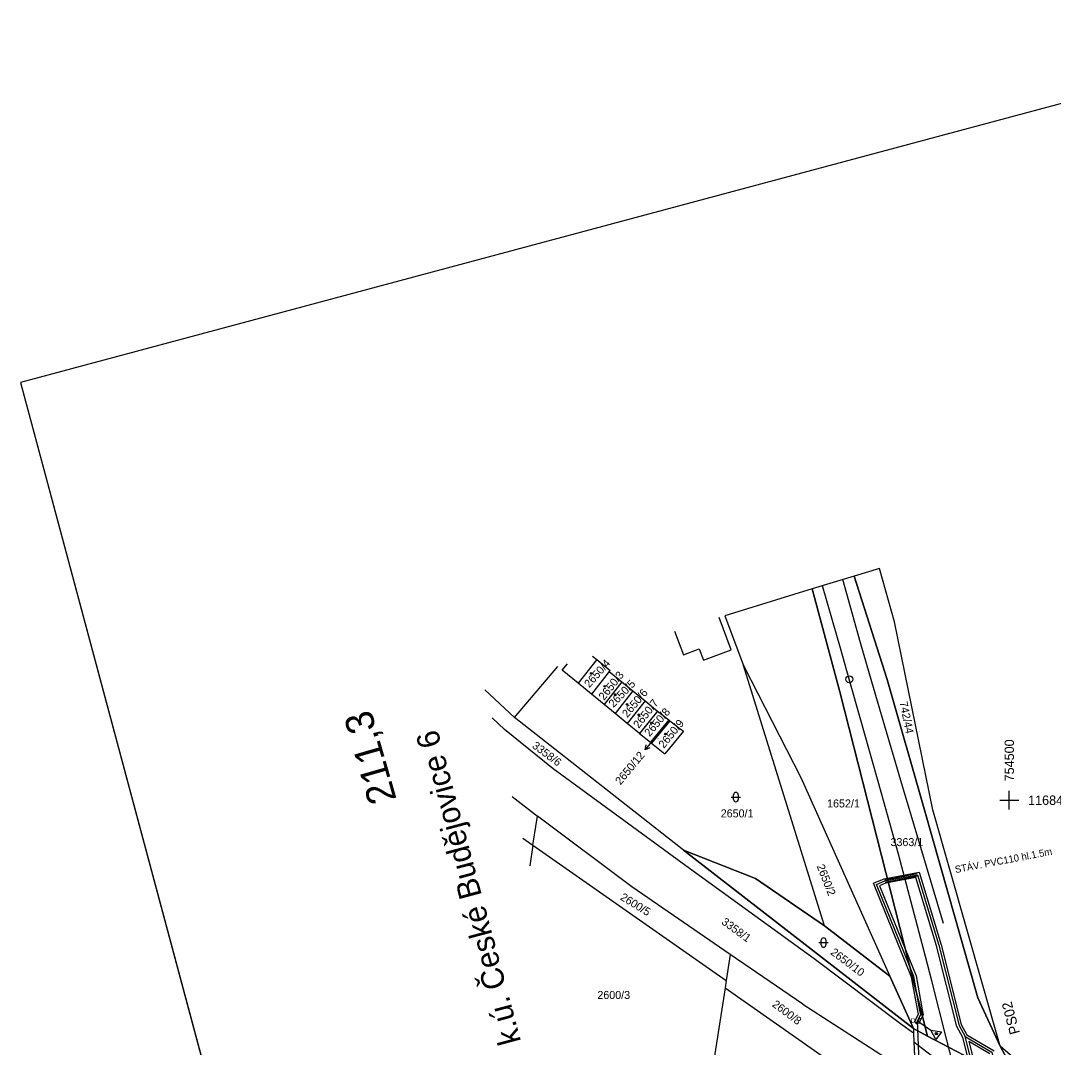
# Model space of a CAD drawing. Extents: x -754710 to -754206, y -1169123 to -1168234.
# Drawn here: x -754710 to -754490.6, y -1168452.5 to -1168234.4 of the extents above; entities that cross this region are included whole.
import ezdxf

# ---------------------------------------------------------------- set-up
doc = ezdxf.new("R2010")
doc.units = 0
for name, color, linetype in [('Implicitní', 7, 'Continuous'), ('Vrstva 1', 7, 'Continuous'), ('Vrstva 10', 7, 'Continuous'), ('Vrstva 16', 7, 'Continuous'), ('Vrstva 18', 7, 'Continuous'), ('Vrstva 19', 7, 'Continuous'), ('Vrstva 24', 7, 'Continuous'), ('Vrstva 25', 7, 'Continuous'), ('Vrstva 3', 7, 'Continuous'), ('Vrstva 36', 7, 'Continuous'), ('Vrstva 4', 7, 'Continuous'), ('Vrstva 45', 7, 'Continuous'), ('Vrstva 6', 7, 'Continuous'), ('Vrstva 61', 7, 'Continuous'), ('Vrstva 7', 7, 'Continuous')]:
    doc.layers.add(name, color=color, linetype=linetype)

msp = doc.modelspace()

# ---------------------------------------------------------------- linework, layer by layer
at = {"layer": 'Implicitní'}
for points in [[(-754500, -1168402), (-754500, -1168400), (-754500, -1168398)], [(-754502, -1168400), (-754500, -1168400), (-754498, -1168400)]]:
    msp.add_lwpolyline(points, dxfattribs=at)
at = {"layer": 'Vrstva 1'}
for p, q in [((-754532.94, -1168352.38), (-754541.88, -1168355.12)), ((-754527.54, -1168350.73), (-754532.94, -1168352.38)), ((-754525.96, -1168374.32), (-754532.94, -1168352.38)), ((-754525.96, -1168374.32), (-754532.94, -1168352.38)), ((-754532.94, -1168352.38), (-754525.96, -1168374.32)), ((-754524.35, -1168362.13), (-754527.54, -1168350.73)), ((-754524.35, -1168362.13), (-754527.54, -1168350.73)), ((-754541.88, -1168355.12), (-754560.43, -1168360.79)), ((-754541.88, -1168355.12), (-754535.97, -1168376.96)), ((-754535.97, -1168376.96), (-754541.88, -1168355.12)), ((-754541.88, -1168355.12), (-754535.97, -1168376.96)), ((-754559.05, -1168368.08), (-754561.6, -1168361.15)), ((-754560.43, -1168360.79), (-754556.45, -1168371.36)), ((-754560.43, -1168360.79), (-754556.45, -1168371.36)), ((-754516.22, -1168402.04), (-754524.35, -1168362.13)), ((-754516.22, -1168402.04), (-754524.35, -1168362.13)), ((-754571.1, -1168364.05), (-754569.24, -1168369.1)), ((-754569.24, -1168369.1), (-754565.87, -1168367.86)), ((-754565.87, -1168367.86), (-754564.99, -1168370.22)), ((-754564.99, -1168370.22), (-754559.05, -1168368.08)), ((-754587.65, -1168370.08), (-754591.61, -1168375.13)), ((-754588.51, -1168369.37), (-754587.65, -1168370.08)), ((-754587.65, -1168370.08), (-754584.81, -1168372.41)), ((-754605.07, -1168382.45), (-754595.87, -1168371.62)), ((-754594.98, -1168372.37), (-754593.82, -1168370.99)), ((-754591.61, -1168375.13), (-754594.98, -1168372.37)), ((-754584.81, -1168372.41), (-754585, -1168372.64)), ((-754556.45, -1168371.36), (-754544.26, -1168395.2)), ((-754556.45, -1168371.36), (-754544.26, -1168395.2)), ((-754539.25, -1168426.67), (-754556.45, -1168371.36)), ((-754585, -1168372.64), (-754588.78, -1168377.44)), ((-754585, -1168372.64), (-754582.27, -1168374.88)), ((-754517.96, -1168402.36), (-754525.96, -1168374.32)), ((-754517.96, -1168402.36), (-754525.96, -1168374.32)), ((-754525.96, -1168374.32), (-754517.96, -1168402.36)), ((-754611.39, -1168376.55), (-754605.07, -1168382.45)), ((-754588.78, -1168377.44), (-754591.61, -1168375.13)), ((-754582.27, -1168374.88), (-754586.03, -1168379.68)), ((-754579.95, -1168376.79), (-754583.73, -1168381.56)), ((-754582.27, -1168374.88), (-754579.95, -1168376.79)), ((-754579.95, -1168376.79), (-754577.36, -1168378.91)), ((-754586.03, -1168379.68), (-754588.78, -1168377.44)), ((-754577.36, -1168378.91), (-754581.15, -1168383.67)), ((-754577.36, -1168378.91), (-754574.73, -1168381.07)), ((-754535.97, -1168376.96), (-754517.36, -1168450.11)), ((-754517.36, -1168450.11), (-754535.97, -1168376.96)), ((-754535.97, -1168376.96), (-754517.36, -1168450.11)), ((-754583.73, -1168381.56), (-754586.03, -1168379.68)), ((-754574.73, -1168381.07), (-754578.54, -1168385.8)), ((-754574.73, -1168381.07), (-754572.35, -1168382.93)), ((-754609.88, -1168382.47), (-754607.22, -1168384.99)), ((-754569.24, -1168410.61), (-754605.07, -1168382.45)), ((-754581.15, -1168383.67), (-754583.73, -1168381.56)), ((-754572.35, -1168382.93), (-754576.2, -1168387.69)), ((-754572.09, -1168383.13), (-754575.98, -1168387.89)), ((-754572.35, -1168382.93), (-754572.09, -1168383.13)), ((-754572.09, -1168383.13), (-754569.96, -1168384.76)), ((-754596.9, -1168393.33), (-754607.22, -1168384.99)), ((-754578.54, -1168385.8), (-754581.15, -1168383.67)), ((-754569.23, -1168385.32), (-754573.19, -1168390.17)), ((-754569.96, -1168384.76), (-754569.23, -1168385.32)), ((-754578.54, -1168385.8), (-754576.2, -1168387.69)), ((-754576.2, -1168387.69), (-754575.98, -1168387.89)), ((-754575.98, -1168387.89), (-754573.86, -1168389.59)), ((-754573.86, -1168389.59), (-754573.19, -1168390.17)), ((-754568.69, -1168413.91), (-754596.9, -1168393.33)), ((-754544.26, -1168395.2), (-754525.37, -1168437.38)), ((-754544.26, -1168395.2), (-754525.37, -1168437.38)), ((-754605.62, -1168399.22), (-754600.23, -1168403.42)), ((-754506.68, -1168442.02), (-754517.96, -1168402.36)), ((-754517.96, -1168402.36), (-754506.68, -1168442.02)), ((-754506.68, -1168442.02), (-754517.96, -1168402.36)), ((-754501.97, -1168452.25), (-754516.22, -1168402.04)), ((-754501.97, -1168452.25), (-754516.22, -1168402.04)), ((-754601.19, -1168409.58), (-754600.23, -1168403.42)), ((-754580.15, -1168418.44), (-754600.23, -1168403.42)), ((-754603.37, -1168408.06), (-754601.19, -1168409.58)), ((-754601.19, -1168409.58), (-754601.87, -1168413.94)), ((-754601.19, -1168409.58), (-754560.12, -1168438.32)), ((-754569.24, -1168410.61), (-754553.89, -1168416.63)), ((-754569.24, -1168410.61), (-754520.37, -1168448.54)), ((-754553.89, -1168416.63), (-754569.24, -1168410.61)), ((-754520.37, -1168448.54), (-754569.24, -1168410.61)), ((-754541.48, -1168433.71), (-754568.69, -1168413.91)), ((-754559.26, -1168432.78), (-754580.15, -1168418.44)), ((-754553.89, -1168416.63), (-754539.25, -1168426.67)), ((-754539.25, -1168426.67), (-754553.89, -1168416.63)), ((-754525.37, -1168437.38), (-754539.25, -1168426.67)), ((-754539.25, -1168426.67), (-754525.37, -1168437.38)), ((-754559.26, -1168432.78), (-754560.12, -1168438.32)), ((-754543.86, -1168443.35), (-754559.26, -1168432.78)), ((-754523.09, -1168447.51), (-754541.48, -1168433.71)), ((-754560.12, -1168438.32), (-754560.36, -1168439.85)), ((-754525.37, -1168437.38), (-754520.37, -1168448.54)), ((-754520.37, -1168448.54), (-754525.37, -1168437.38)), ((-754525.37, -1168437.38), (-754520.37, -1168448.54)), ((-754560.36, -1168439.85), (-754563.64, -1168460.96)), ((-754501.97, -1168452.25), (-754506.68, -1168442.02)), ((-754506.68, -1168442.02), (-754501.97, -1168452.25)), ((-754506.68, -1168442.02), (-754501.97, -1168452.25)), ((-754543.86, -1168443.35), (-754519.95, -1168458.75)), ((-754520.33, -1168449.52), (-754523.09, -1168447.51)), ((-754520.37, -1168448.54), (-754517.36, -1168450.11)), ((-754520.37, -1168448.54), (-754517.36, -1168450.11)), ((-754520.37, -1168448.54), (-754520.33, -1168449.52)), ((-754520.33, -1168449.52), (-754520.25, -1168451.35)), ((-754520.25, -1168451.35), (-754519.95, -1168458.75)), ((-754517.36, -1168450.11), (-754497.45, -1168460.53)), ((-754517.36, -1168450.11), (-754497.45, -1168460.53)), ((-754497.45, -1168460.53), (-754501.97, -1168452.25)), ((-754501.97, -1168452.25), (-754497.45, -1168460.53)), ((-754480.66, -1168470.56), (-754501.97, -1168452.25))]:
    msp.add_line(p, q, dxfattribs=at)
for points in [[(-754483.58, -1168568.3), (-754489.69, -1168544.13), (-754495.86, -1168519.7), (-754500.17, -1168502.64), (-754500.22, -1168502.46), (-754500.39, -1168501.79), (-754506.63, -1168477.15), (-754508.73, -1168468.84), (-754512.62, -1168453.46), (-754513.24, -1168451.02), (-754516.47, -1168438.36), (-754517.79, -1168433.24), (-754523.55, -1168411.48), (-754527.19, -1168398.27), (-754531.51, -1168382.98), (-754533.99, -1168374.26), (-754535.88, -1168367.71), (-754539.68, -1168354.44)], [(-754513.99, -1168426.21), (-754518.82, -1168410.04), (-754522.69, -1168397.05), (-754527.17, -1168381.88), (-754529.7, -1168373.15), (-754531.6, -1168366.53), (-754535.37, -1168353.13)], [(-754519.17, -1168455.59), (-754519.47, -1168446.86)], [(-754452.67, -1168639.96), (-754460.6, -1168619.67), (-754483.21, -1168541.23), (-754494.84, -1168494.63), (-754493.82, -1168481.8), (-754494.32, -1168478.89), (-754494.55, -1168477.55), (-754496.03, -1168468.86), (-754496.32, -1168467.13), (-754496.66, -1168465.16), (-754497.45, -1168460.53), (-754517.36, -1168450.11), (-754520.37, -1168448.54), (-754520.33, -1168449.52), (-754520.25, -1168451.35), (-754519.95, -1168458.75), (-754519.84, -1168461.42), (-754519.8, -1168462.41), (-754486.32, -1168624.94), (-754485.38, -1168629.68)]]:
    msp.add_lwpolyline(points, dxfattribs=at)
msp.add_circle((-754533.98, -1168374.3), 0.75, dxfattribs=at)
at = {"layer": 'Vrstva 10'}
for points in [[(-754508.81, -1168454.58), (-754509.87, -1168450.43), (-754511.14, -1168448.05), (-754515.44, -1168430.96), (-754519.87, -1168416.42), (-754526.28, -1168417.64), (-754527.56, -1168418.16), (-754519.79, -1168437.32), (-754518.48, -1168444.57), (-754518.27, -1168445.63), (-754519.26, -1168447.54), (-754520.14, -1168447.08), (-754519.31, -1168445.49), (-754519.46, -1168444.75), (-754520.75, -1168437.6), (-754528.86, -1168417.6), (-754526.56, -1168416.68), (-754519.17, -1168415.28), (-754514.48, -1168430.7), (-754510.2, -1168447.69), (-754509.03, -1168449.86), (-754503.24, -1168453.23)], [(-754504.12, -1168453.89), (-754508.62, -1168451.26), (-754507.63, -1168455.2)]]:
    msp.add_lwpolyline(points, dxfattribs=at)
at = {"layer": 'Vrstva 16'}
msp.add_line((-754577.37, -1168389.32), (-754575.44, -1168387.02), dxfattribs=at)
msp.add_lwpolyline([(-754576.34, -1168388.87), (-754577.37, -1168389.32), (-754577.11, -1168388.23)], dxfattribs=at)
at = {"layer": 'Vrstva 25'}
for p, q in [((-754558.58, -1168399.83), (-754558.58, -1168398.83)), ((-754557.58, -1168398.83), (-754557.58, -1168399.83)), ((-754559.08, -1168399.33), (-754557.08, -1168399.33)), ((-754540.44, -1168430.24), (-754538.44, -1168430.24)), ((-754539.94, -1168430.74), (-754539.94, -1168429.74)), ((-754538.94, -1168429.74), (-754538.94, -1168430.74))]:
    msp.add_line(p, q, dxfattribs=at)
for centre in [(-754588.82, -1168373.06), (-754585.95, -1168375.79), (-754583.72, -1168377.55), (-754581.22, -1168379.63), (-754578.7, -1168381.86), (-754576.01, -1168383.58), (-754574.25, -1168385.53), (-754573.08, -1168385.96)]:
    msp.add_circle(centre, 0.175, dxfattribs=at)
for centre, start, end in [((-754558.08, -1168398.83), 0, 180), ((-754558.08, -1168399.83), 180, 0), ((-754539.44, -1168429.74), 0, 180), ((-754539.44, -1168430.74), 180, 0)]:
    msp.add_arc(centre, 0.5, start, end, dxfattribs=at)
at = {"layer": 'Vrstva 3'}
msp.add_lwpolyline([(-754710.01, -1168311.22), (-754492.6, -1169122.6), (-754205.72, -1169045.73), (-754423.13, -1168234.35)], close=True, dxfattribs=at)
at = {"layer": 'Vrstva 36'}
for points in [[(-754526.47, -1168416.91), (-754519.57, -1168415.6)], [(-754526.37, -1168417.41), (-754519.47, -1168416.1)]]:
    msp.add_lwpolyline(points, dxfattribs=at)
at = {"layer": 'Vrstva 4'}
for p, q in [((-754519.02, -1168446.23), (-754519.92, -1168447.5)), ((-754520.25, -1168451.35), (-754516.61, -1168454.2)), ((-754515.54, -1168449.39), (-754515.46, -1168449.88))]:
    msp.add_line(p, q, dxfattribs=at)
msp.add_lwpolyline([(-754519.47, -1168446.86), (-754516.63, -1168448.87), (-754514.42, -1168449.22), (-754515.57, -1168450.86), (-754516.63, -1168448.87)], dxfattribs=at)
msp.add_circle((-754515.5, -1168449.63), 0.248, dxfattribs=at)
at = {"layer": 'Vrstva 45'}
for points in [[(-754519.47, -1168446.86), (-754518.79, -1168445.56), (-754518.97, -1168444.66), (-754520.27, -1168437.46), (-754528.21, -1168417.88), (-754526.42, -1168417.16), (-754519.52, -1168415.85), (-754514.96, -1168430.83), (-754510.67, -1168447.87), (-754509.4, -1168450.23)], [(-754503.77, -1168472.48), (-754509.4, -1168450.23)], [(-754509.4, -1168450.23), (-754503.68, -1168453.56), (-754502.47, -1168458.49), (-754501.99, -1168458.81)]]:
    msp.add_lwpolyline(points, dxfattribs=at)
at = {"layer": 'Vrstva 6'}
msp.add_line((-754560.36, -1168439.85), (-754531.99, -1168459.75), dxfattribs=at)
at = {"layer": 'Vrstva 61'}
msp.add_line((-754710.01, -1168311.22), (-754492.6, -1169122.6), dxfattribs=at)
msp.add_lwpolyline([(-754492.6, -1169122.6), (-754205.72, -1169045.73), (-754423.13, -1168234.35), (-754710.01, -1168311.22)], dxfattribs=at)

# ---------------------------------------------------------------- texts
at = {"layer": 'Implicitní'}
msp.add_text('754500', height=2, rotation=90, dxfattribs=at).set_placement((-754499, -1168396))
msp.add_text('1168400', height=2, dxfattribs=at).set_placement((-754496, -1168401))
at = {"layer": 'Vrstva 16'}
msp.add_text('2650/12', height=1.7, rotation=50.4203, dxfattribs=at).set_placement((-754582.58, -1168396.86))
at = {"layer": 'Vrstva 18'}
for s, rotation, p in [('742/44', 281.5141, (-754523.33, -1168379.17)), ('3358/6', 323.0909, (-754601.5, -1168388.73)), ('2650/2', 291.5782, (-754540.94, -1168414.02)), ('2600/5', 328.4767, (-754582.79, -1168421.04)), ('3358/1', 323.8882, (-754561.28, -1168426.18)), ('2650/10', 323.0909, (-754538.12, -1168432.62)), ('2600/8', 323.0909, (-754550.51, -1168443.68))]:
    msp.add_text(s, height=1.7, rotation=rotation, dxfattribs=at).set_placement(p)
for s, p in [('1652/1', (-754538.7, -1168401.54)), ('2650/1', (-754561.29, -1168403.65)), ('3363/1', (-754525.23, -1168409.75)), ('2600/3', (-754587.5, -1168442.23))]:
    msp.add_text(s, height=1.7, dxfattribs=at).set_placement(p)
at = {"layer": 'Vrstva 19'}
for s, rotation, p in [('2650/4', 48.4149, (-754589.21, -1168376.21)), ('2650/3', 51.6808, (-754586.06, -1168378.9)), ('2650/5', 46.1804, (-754584.08, -1168380.42)), ('2650/6', 50.0765, (-754581.12, -1168382.56)), ('2650/7', 51.5662, (-754578.71, -1168384.85)), ('2650/8', 49.6754, (-754576.4, -1168386.61)), ('2650/9', 50.7068, (-754573.37, -1168389.1))]:
    msp.add_text(s, height=1.7, rotation=rotation, dxfattribs=at).set_placement(p)
msp.add_text('2650/12', height=0.2, dxfattribs=at).set_placement((-754575.4, -1168387.01))
at = {"layer": 'Vrstva 24'}
msp.add_text('k.ú. České Budějovice 6', height=4.8, rotation=105, dxfattribs=at).set_placement((-754603.68, -1168451.27))
at = {"layer": 'Vrstva 3'}
msp.add_text('PS02', height=2.16, rotation=105, dxfattribs=at).set_placement((-754497.72, -1168449.44))
at = {"layer": 'Vrstva 36'}
msp.add_text('STÁV. PVC110 hl.1.5m', height=1.5, rotation=10.75, dxfattribs=at).set_placement((-754511.4, -1168415.49))
at = {"layer": 'Vrstva 4'}
msp.add_text('D', height=1, dxfattribs=at).set_placement((-754520.91, -1168447.32))
at = {"layer": 'Vrstva 7'}
msp.add_text('211,3', height=6, rotation=106.0493, dxfattribs=at).set_placement((-754630.11, -1168399.82))

doc.saveas('drawing.dxf')
